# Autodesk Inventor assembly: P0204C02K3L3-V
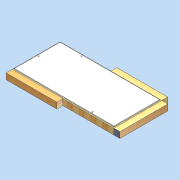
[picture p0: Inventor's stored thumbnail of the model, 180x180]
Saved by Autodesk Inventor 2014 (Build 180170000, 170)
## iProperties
Created: 2011-04
Part Number: P0204C02K3L3-V
Document SubType Name: Assembly
Designer: david.appleford
Mass: 17000 g
Surface Area: 20118.7 cm^2
Volume: 59127.5 cm^3
Density: 0.287514 g/cm^3
Description: 0.5w x 1w 02 Ceiling Panel - 3 Locks 3 Lugs
Cost Center: £77.00
Justset: False
Title: 0.5w x 1w 02 Ceiling Panel - 3 Locks 3 Lugs
Author: david.appleford
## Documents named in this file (4)
- C:\Documents and Settings\john.everitt\Local Settings\My Documents\Vault\Production MkII\VIRTUAL ELEMENTS\Virtual Ceilings\Ceiling MgO & Timber Frame\P0204C02K3L3-V.iam
- C:\Documents and Settings\john.everitt\Local Settings\My Documents\Vault\Production MkII\VIRTUAL ELEMENTS\Virtual Lugs\Superceded Lugs\LA02C3V.ipt
- C:\Documents and Settings\john.everitt\Local Settings\My Documents\Vault\Production MkII\VIRTUAL ELEMENTS\Virtual Lugs\Superceded Lugs\LA02E3V.ipt
- C:\Documents and Settings\john.everitt\Local Settings\My Documents\Vault\Production MkII\VIRTUAL ELEMENTS\Virtual Ceilings\Ceiling MgO & Timber Frame\P0204C02K3-V.ipt
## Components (4 placed, 3 different names)
1. P0204C02K3-V:1 — Mate:1, Flush:1, Flush:2, Mate:2, Flush:3, Flush:4, Mate:4, Flush:7, Flush:8
2. LA02E3V:1 — Mate:1, Flush:1, Flush:2
3. LA02C3V:2 — Mate:2, Flush:3, Flush:4
4. LA02C3V:3 — Mate:4, Flush:7, Flush:8
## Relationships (9: Flush 6, Mate 3)
- Mate:1: P0204C02K3-V:1 ↔ LA02E3V:1
- Flush:1: P0204C02K3-V:1 ↔ LA02E3V:1
- Flush:2: P0204C02K3-V:1 ↔ LA02E3V:1
- Mate:2: P0204C02K3-V:1 ↔ LA02C3V:2
- Flush:3: P0204C02K3-V:1 ↔ LA02C3V:2
- Flush:4: P0204C02K3-V:1 ↔ LA02C3V:2
- Mate:4: P0204C02K3-V:1 ↔ LA02C3V:3
- Flush:7: P0204C02K3-V:1 ↔ LA02C3V:3
- Flush:8: P0204C02K3-V:1 ↔ LA02C3V:3
## Named parameters: t = 1 mm, Cl = 2 mm
